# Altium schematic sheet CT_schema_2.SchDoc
size 461 x 327 mm
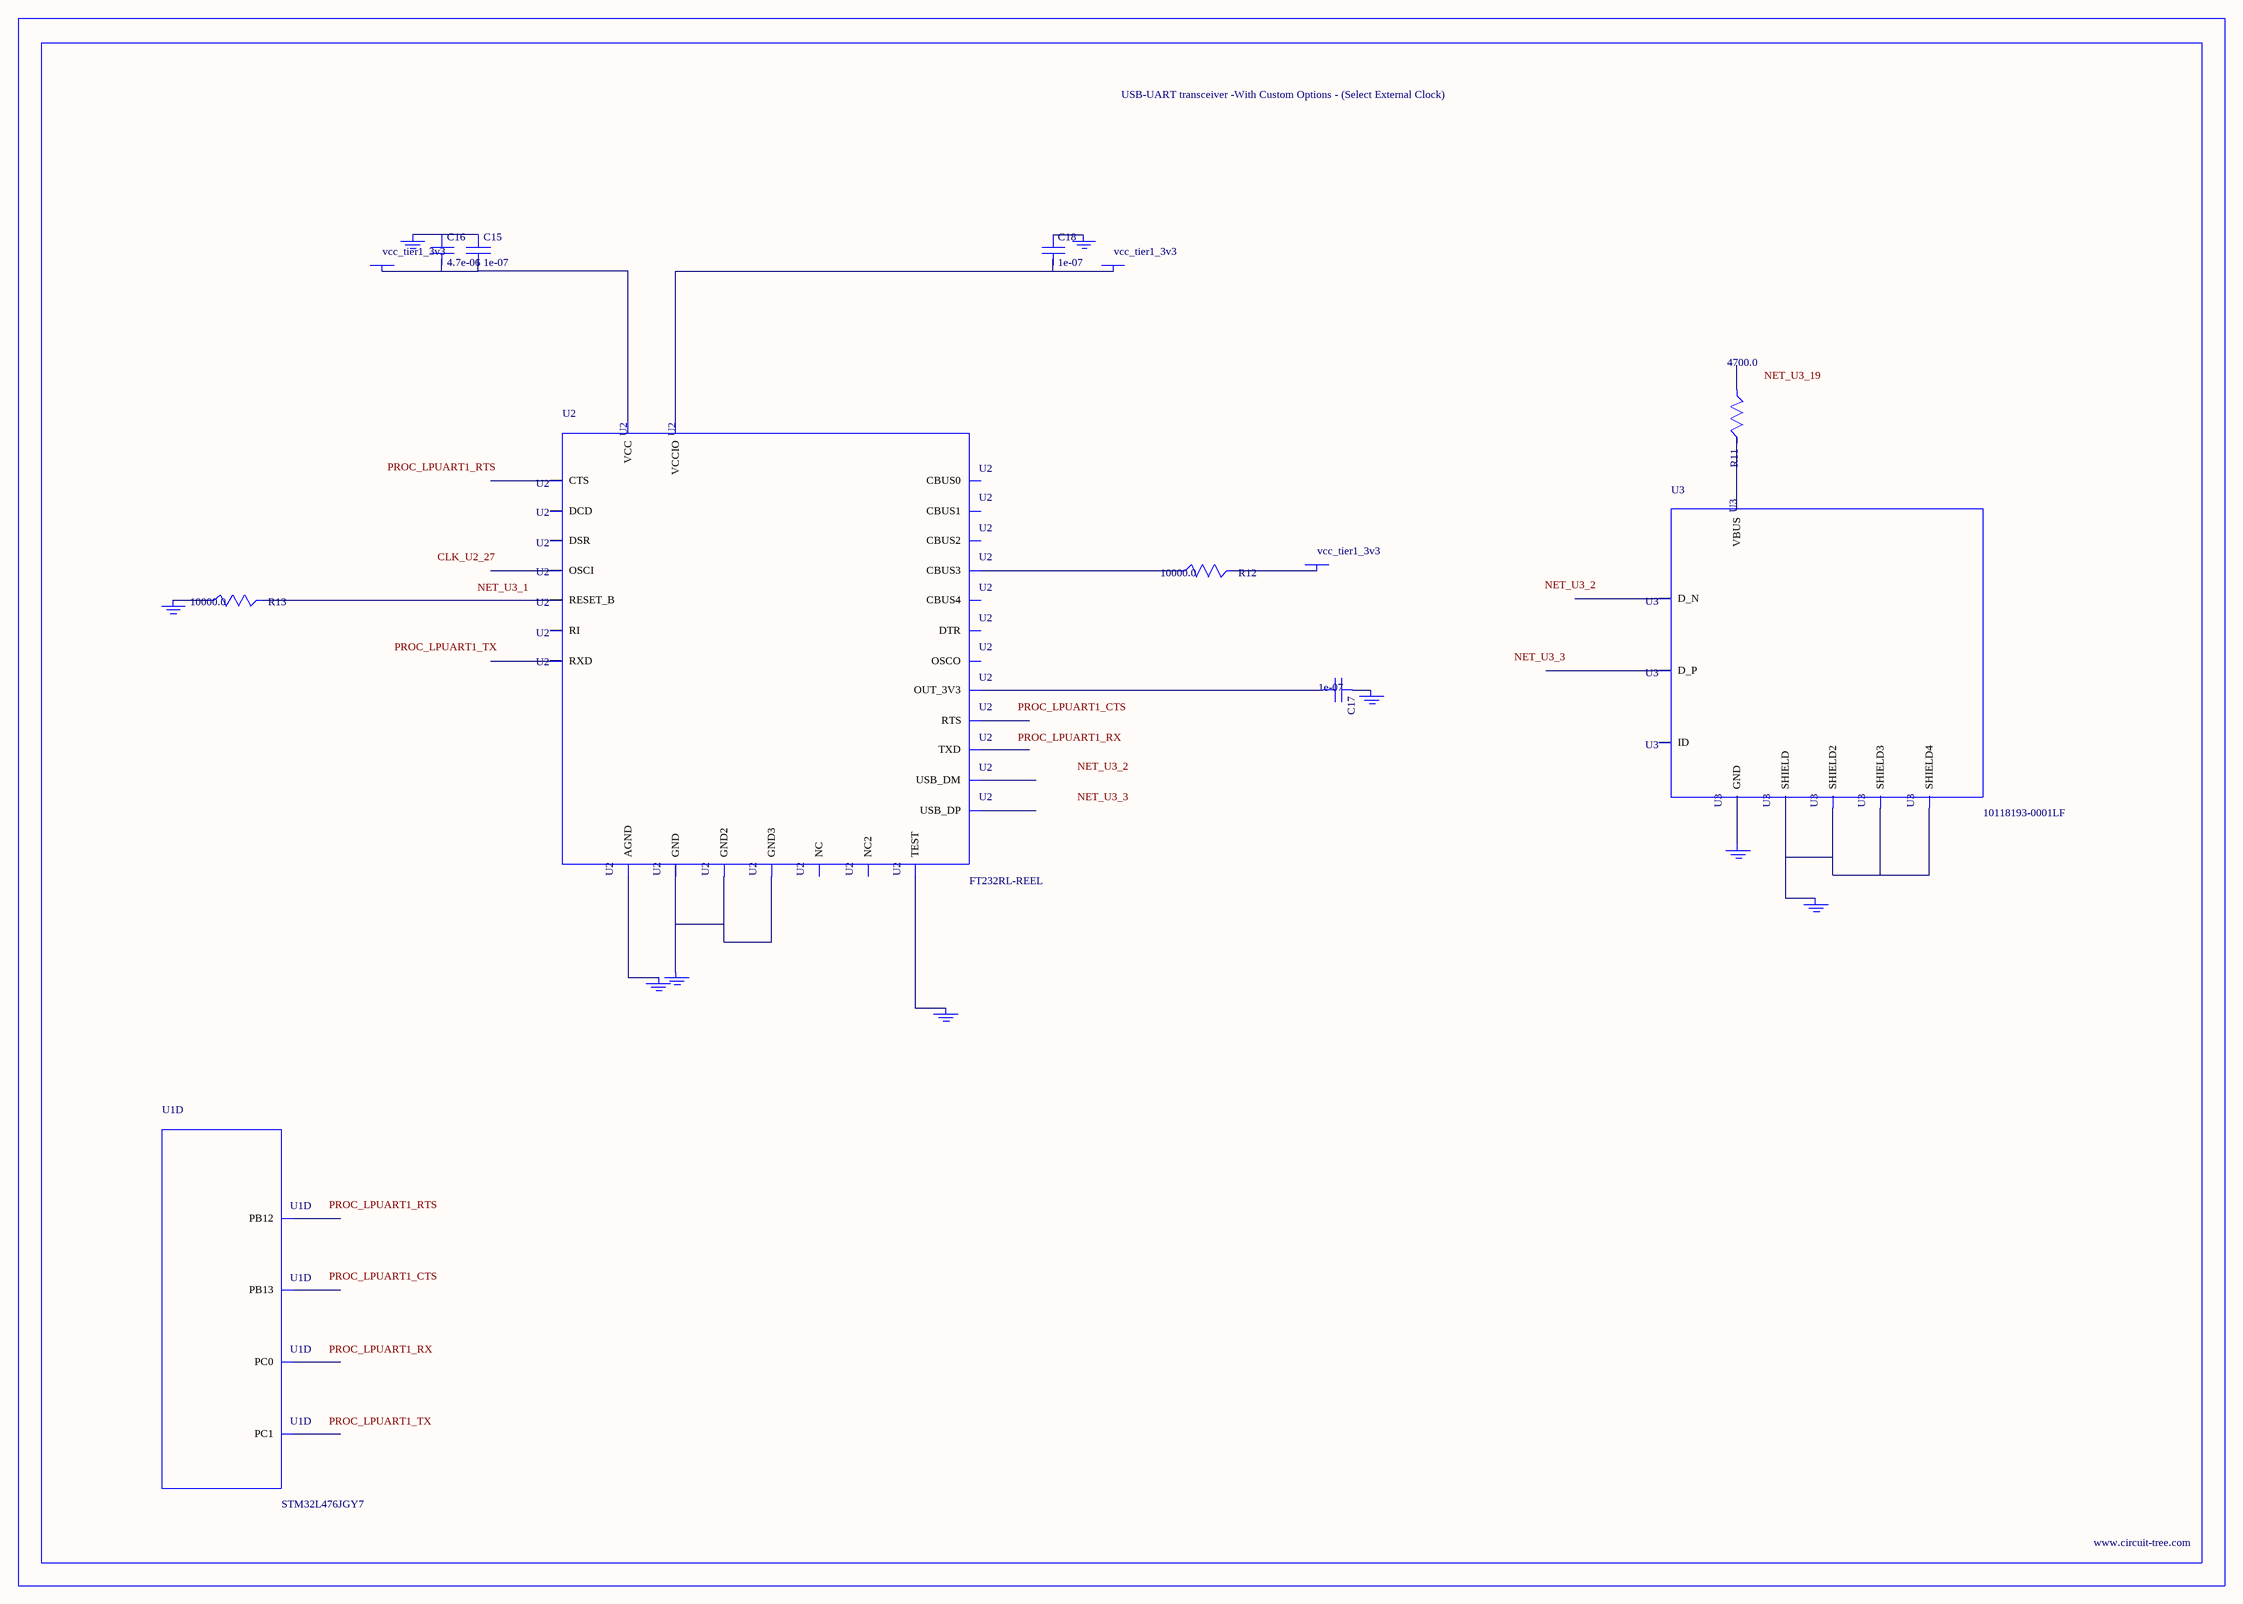
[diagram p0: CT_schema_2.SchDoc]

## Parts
BORDER1  (no value)
C15  1e-07  [C0402]
C16  4.7e-06  [C0805]
C17  1e-07  [C0402]
C18  1e-07  [C0402]
GND_INSTANCE_1_0  (no value)
GND_INSTANCE_1_1  (no value)
GND_INSTANCE_1_2  (no value)
GND_INSTANCE_1_3  (no value)
GND_INSTANCE_1_4  (no value)
GND_INSTANCE_1_5  (no value)
GND_INSTANCE_1_6  (no value)
GND_INSTANCE_1_7  (no value)
GND_INSTANCE_1_8  (no value)
POWER_INSTANCE_1_0  vcc_tier1_3v3
POWER_INSTANCE_1_1  vcc_tier1_3v3
POWER_INSTANCE_1_2  vcc_tier1_3v3
R11  4700.0  [R0603]
R12  10000.0  [R0603]
R13  10000.0  [R0603]
U1  STM32L476JGY7  [WLCSP72]  (part D of 8)
U2  FT232RL-REEL  [SSOP-28]
U3  10118193-0001LF  [FCI_10118193-0001LF]

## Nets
NetC15_1: C15.1 C16.1 GND_INSTANCE_1_3.0(GND)
NetC15_2: C15.2 C16.2 POWER_INSTANCE_1_2.0(PWR) U2.20(VCC)
NetC17_1: C17.1 GND_INSTANCE_1_1.0(GND)
NetC17_2: C17.2 U2.17(OUT_3V3)
NetC18_1: C18.1 GND_INSTANCE_1_0.0(GND)
NetC18_2: C18.2 POWER_INSTANCE_1_0.0(PWR) U2.4(VCCIO)
NetGND_INSTANCE_1_2_0: GND_INSTANCE_1_2.0(GND) R13.1
NetGND_INSTANCE_1_4_0: GND_INSTANCE_1_4.0(GND) U2.25(AGND)
NetGND_INSTANCE_1_5_0: GND_INSTANCE_1_5.0(GND) U2.26(TEST)
NetGND_INSTANCE_1_6_0: GND_INSTANCE_1_6.0(GND) U2.7(GND) U2.18(GND2) U2.21(GND3)
NetGND_INSTANCE_1_7_0: GND_INSTANCE_1_7.0(GND) U3.6(SHIELD) U3.7(SHIELD2) U3.8(SHIELD3) U3.9(SHIELD4)
NetGND_INSTANCE_1_8_0: GND_INSTANCE_1_8.0(GND) U3.5(GND)
NetPOWER_INSTANCE_1_1_0: POWER_INSTANCE_1_1.0(PWR) R12.2
NetR11_2: R11.2 U3.1(VBUS)
NetR12_1: R12.1 U2.14(CBUS3)
NetR13_2: R13.2 U2.19(RESET_B)

Not connected (* = marked no-connect by the designer): R11 1; U1 F8(PC1) F9(PC0) H1(PB12) H2(PB13); U2 1(TXD) 2(DTR) 3(RTS) 5(RXD) 6(RI) 8(NC) 9(DSR) 10(DCD) 11(CTS) 12(CBUS4) 13(CBUS2) 15(USB_DP) 16(USB_DM) 22(CBUS1) 23(CBUS0) 24(NC2) 27(OSCI) 28(OSCO); U3 2(D_N) 3(D_P) 4(ID)

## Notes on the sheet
- Labels drawn without touching a wire or pin: CLK_U2_27, NET_U3_1, NET_U3_2, NET_U3_3, NET_U3_19, PROC_LPUART1_CTS, PROC_LPUART1_RTS, PROC_LPUART1_RX, PROC_LPUART1_TX

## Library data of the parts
BORDER1 = BORDER_PAGE1
C15 C17 C18 = C0402C104K3RACTU
C16 = C0805C475K4RACTU
GND_INSTANCE_1_0-GND_INSTANCE_1_8 = GND
POWER_INSTANCE_1_0-POWER_INSTANCE_1_2 = PWR
R11 = RC0603JR-074K7L
R12 R13 = RC0603JR-0710KL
